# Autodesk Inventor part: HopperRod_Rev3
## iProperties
Created: 2009-01
Part Number: HopperRod_Rev3
Document SubType Name: Modeling
Designer: claivier
Norme de conversion: STEP AP214IS
Nom du fichier: HopperRod_Rev3.STEP
Préprocesseur: SolidWorks 2008
Postprocesseur: Build: 344a, Release: 11 SP2 - Date: Fri 08/18/2006
Unités envoyées: INCHES
Incertitude: 1e-05
Author: claivier
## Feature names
1. Base1
